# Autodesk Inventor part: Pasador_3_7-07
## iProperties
Company: COMGRAP
Created: 2008-01
Part Number: Pasador_3_7-07
Material: ABS Plastic
Document SubType Name: Modeling
Designer: eruiz-tagle
Mass: 0.249535 g
Surface Area: 3.24985 cm^2
Volume: 0.235411 cm^3
Density: 1.06 g/cm^3
Title: CURSO INVENTOR
Author: Esteban
Comments: Esta pieza fue creada en el curso de inventor
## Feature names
1. Derived Body1 [Tagging]
